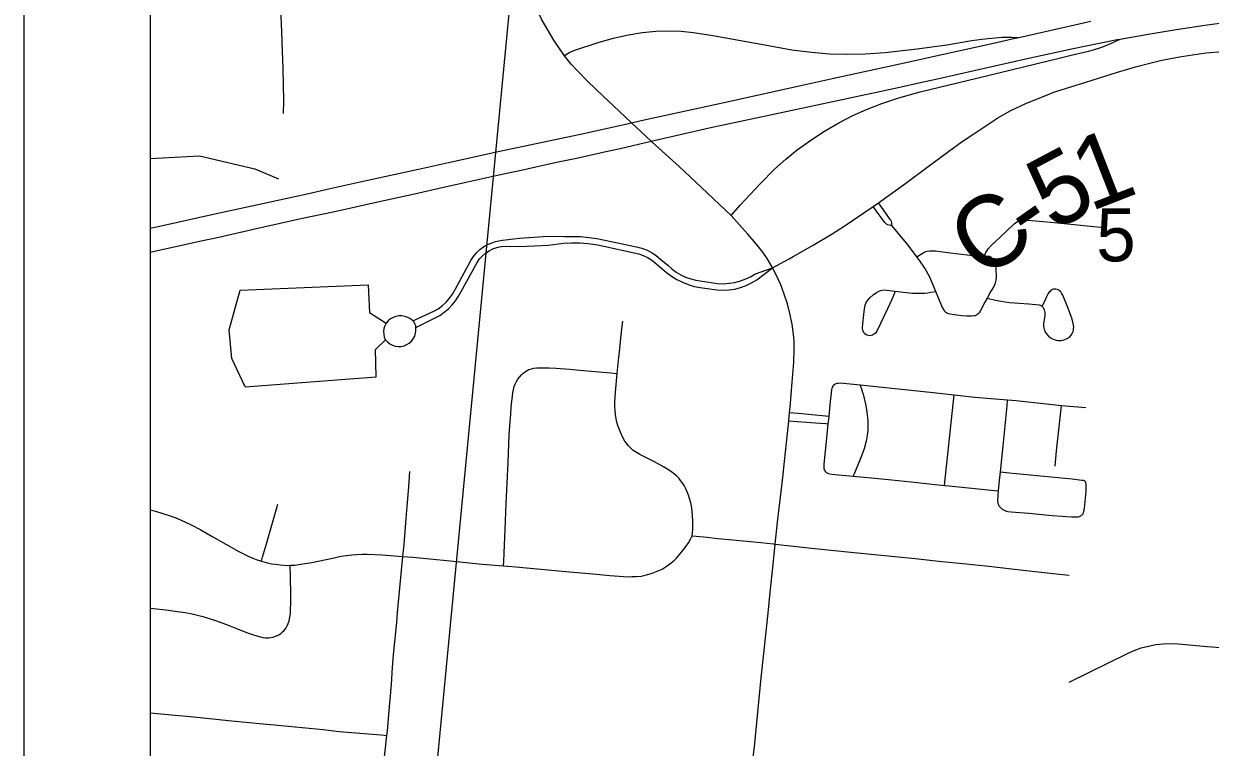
# Model space of a CAD drawing. Extents: x 0 to 34, y 0 to 22.
# Drawn here: x 22.416 to 23.354, y 13.976 to 14.548 of the extents above; entities that cross this region are included whole.
import ezdxf

# ---------------------------------------------------------------- set-up
doc = ezdxf.new("R2010")
doc.units = 0
for name, color, linetype in [('GM_X_City_Street', 7, 'Continuous'), ('GM_X_County_Road', 7, 'Continuous'), ('GM_X_County_Road_Text', 7, 'Continuous'), ('GM_X_Interchange_Ramps', 7, 'Continuous'), ('GM_X_Interstate_Route', 7, 'Continuous'), ('GM_X_Minor_River', 7, 'Continuous'), ('GM_X_Section', 7, 'Continuous'), ('GM_X_Section_Text', 7, 'Continuous'), ('SH_Border', 7, 'Continuous'), ('SH_Data', 7, 'Continuous')]:
    doc.layers.add(name, color=color, linetype=linetype)

msp = doc.modelspace()

# ---------------------------------------------------------------- linework, layer by layer
at = {"layer": 'GM_X_City_Street'}
for p, q in [((22.58739, 14.33718), (22.68845, 14.34132)), ((22.59139, 14.26067), (22.69501, 14.26859))]:
    msp.add_line(p, q, dxfattribs=at)
for points in [[(22.62172, 14.47673), (22.6219, 14.48664), (22.62129, 14.5124), (22.62056, 14.53306), (22.62023, 14.54176), (22.61961, 14.55852), (22.61954, 14.56349), (22.6202, 14.57179), (22.62145, 14.58727), (22.62216, 14.59842), (22.62247, 14.60549), (22.62223, 14.60887), (22.62184, 14.61264), (22.62153, 14.61578), (22.62078, 14.62011)], [(23.10245, 14.3882), (23.10128, 14.38825), (23.10023, 14.38836), (23.0993, 14.38868), (23.09833, 14.38921), (23.09764, 14.38974), (23.09695, 14.39055), (23.09473, 14.39346), (23.0917, 14.39775), (23.08779, 14.40327)], [(23.10245, 14.3882), (23.10241, 14.38934), (23.10233, 14.39027), (23.10206, 14.39135), (23.10156, 14.39237), (23.10116, 14.39297), (23.09587, 14.40054), (23.09197, 14.40612)], [(23.12209, 14.36354), (23.1152, 14.37267), (23.10245, 14.3882)], [(23.17561, 14.36415), (23.17623, 14.36564), (23.17671, 14.36682), (23.17719, 14.36762), (23.17773, 14.36848), (23.17864, 14.36977), (23.18089, 14.37229), (23.18833, 14.37937), (23.19922, 14.38957), (23.20133, 14.39112), (23.20208, 14.39157), (23.20328, 14.39209), (23.20445, 14.3925), (23.2057, 14.39266), (23.20702, 14.39266), (23.23064, 14.39062), (23.26993, 14.38661)], [(22.72394, 14.31296), (22.74046, 14.32042), (22.74394, 14.32251), (22.74719, 14.32494), (22.75019, 14.32769), (22.75288, 14.33073), (22.75527, 14.33401), (22.75731, 14.33753), (22.76978, 14.36054), (22.77173, 14.36371), (22.77407, 14.36661), (22.77676, 14.36919), (22.77974, 14.37141), (22.78299, 14.37323), (22.78644, 14.37462), (22.7891, 14.37556), (22.79184, 14.37624), (22.79463, 14.37668), (22.80808, 14.37829), (22.83063, 14.37989), (22.84374, 14.37943), (22.85014, 14.3796), (22.85653, 14.37941), (22.8629, 14.37885), (22.86924, 14.37795), (22.87551, 14.37668), (22.90069, 14.37147), (22.90493, 14.37032), (22.90901, 14.36872), (22.9129, 14.36669), (22.91656, 14.36426), (22.91993, 14.36145), (22.92531, 14.35676), (22.92851, 14.35396), (22.93196, 14.35146), (22.93562, 14.34929), (22.93947, 14.34747), (22.94346, 14.34601), (22.94758, 14.34491), (22.96469, 14.34236), (22.96926, 14.34224), (22.97382, 14.34254), (22.97834, 14.34328), (22.98276, 14.34444), (22.98706, 14.34601), (22.99119, 14.34798), (22.994, 14.34972), (23.00815, 14.35477)], [(22.72629, 14.30772), (22.74514, 14.31718), (22.74867, 14.31963), (22.75196, 14.3224), (22.75497, 14.32546), (22.75768, 14.32878), (22.76007, 14.33235), (22.76212, 14.33613), (22.77464, 14.35911), (22.77658, 14.36183), (22.77884, 14.36429), (22.78139, 14.36645), (22.78419, 14.36828), (22.78719, 14.36976), (22.79035, 14.37084), (22.79362, 14.37153), (22.79695, 14.37182), (22.80856, 14.37163), (22.83106, 14.37258), (22.84296, 14.37436), (22.84934, 14.37463), (22.85574, 14.37452), (22.86211, 14.37402), (22.86844, 14.37315), (22.87471, 14.37191), (22.89879, 14.36673), (22.90242, 14.36586), (22.90592, 14.36461), (22.90928, 14.363), (22.91244, 14.36104), (22.9154, 14.35877), (22.92071, 14.35426), (22.9244, 14.35102), (22.92834, 14.3481), (22.93253, 14.34554), (22.93692, 14.34335), (22.94148, 14.34155), (22.94618, 14.34014), (22.95099, 14.33915), (22.96423, 14.33733), (22.96895, 14.33709), (22.97366, 14.33732), (22.97833, 14.33802), (22.98291, 14.33918), (22.98736, 14.34079), (22.99161, 14.34283), (22.99565, 14.34529), (23.00815, 14.35477)], [(23.12209, 14.36354), (23.12721, 14.36674), (23.12823, 14.36726), (23.1292, 14.36769), (23.13041, 14.36803), (23.13214, 14.36828), (23.13452, 14.36827), (23.13693, 14.36811), (23.14669, 14.36679), (23.16401, 14.36469), (23.17561, 14.36415)], [(23.13717, 14.33615), (23.13516, 14.34102), (23.13233, 14.34732), (23.12841, 14.35447), (23.12459, 14.36022), (23.12209, 14.36354)], [(23.17561, 14.36415), (23.17654, 14.3641), (23.17883, 14.36399), (23.17947, 14.36389), (23.1802, 14.36365), (23.18101, 14.36316), (23.18153, 14.36272), (23.18218, 14.36211), (23.1827, 14.36134), (23.18308, 14.36074), (23.18348, 14.35983), (23.18384, 14.35896), (23.18421, 14.35765), (23.18457, 14.35471), (23.18477, 14.34735), (23.18455, 14.34501), (23.18437, 14.34391), (23.18402, 14.34272), (23.1829, 14.33999), (23.18075, 14.3363), (23.17769, 14.33071)], [(22.68845, 14.34132), (22.68971, 14.31959), (22.70267, 14.31106)], [(23.17769, 14.33071), (23.18446, 14.32926), (23.18862, 14.32836), (23.1953, 14.32748), (23.21072, 14.3263), (23.2189, 14.32556), (23.21961, 14.32537), (23.22033, 14.32502), (23.22101, 14.32453), (23.2215, 14.32405), (23.222, 14.32341), (23.22233, 14.32284), (23.22286, 14.32153), (23.22323, 14.31951), (23.22323, 14.31687), (23.22238, 14.31073), (23.22234, 14.3084), (23.22247, 14.30741), (23.22269, 14.30643), (23.22299, 14.30544), (23.22341, 14.30437), (23.22402, 14.30347), (23.22465, 14.30262), (23.22614, 14.30085), (23.22744, 14.29972), (23.22835, 14.29913), (23.2294, 14.29858), (23.23075, 14.29802), (23.23218, 14.29762), (23.23385, 14.29734), (23.23492, 14.29729), (23.23613, 14.2974), (23.23727, 14.29759), (23.2384, 14.29789), (23.24058, 14.29871), (23.24205, 14.29955), (23.24268, 14.30003), (23.24334, 14.30065), (23.24409, 14.30154), (23.24474, 14.30242), (23.24526, 14.30342), (23.24568, 14.30454), (23.24594, 14.30557), (23.24611, 14.30694), (23.24616, 14.30823), (23.24603, 14.30951), (23.24579, 14.31079), (23.24492, 14.31428), (23.24152, 14.3235), (23.23745, 14.33315), (23.23663, 14.33487), (23.23585, 14.3359), (23.23495, 14.33672), (23.23402, 14.33728), (23.23303, 14.33771), (23.232, 14.33792), (23.23114, 14.33796), (23.23019, 14.33783), (23.22929, 14.33753), (23.22852, 14.33706), (23.22781, 14.33648), (23.22724, 14.3359), (23.22659, 14.33521), (23.22603, 14.33449), (23.22539, 14.33341), (23.22461, 14.33195), (23.22384, 14.32998), (23.22273, 14.32762), (23.22118, 14.32467)], [(22.59139, 14.26067), (22.5809, 14.28319), (22.57861, 14.3057), (22.58739, 14.33718)], [(23.10515, 14.33599), (23.1023, 14.32983), (23.09894, 14.32251), (23.09638, 14.3168), (23.09063, 14.30475), (23.09, 14.30382), (23.08947, 14.30323), (23.0888, 14.30257), (23.08797, 14.30202), (23.08711, 14.30159), (23.08602, 14.30124), (23.08497, 14.30112), (23.08403, 14.3012), (23.08294, 14.30147), (23.08203, 14.30194), (23.08115, 14.30255), (23.08063, 14.30311), (23.08016, 14.30382), (23.07973, 14.30464), (23.07946, 14.30546), (23.0793, 14.30651), (23.07926, 14.30737), (23.07941, 14.31061), (23.0802, 14.31797), (23.08069, 14.32233), (23.08132, 14.3252), (23.08218, 14.32737), (23.0834, 14.32934), (23.08497, 14.33105), (23.08774, 14.33351), (23.09024, 14.33531), (23.09212, 14.33636), (23.09377, 14.33694), (23.09606, 14.33728), (23.09842, 14.33725), (23.11133, 14.33543), (23.11883, 14.33477), (23.12512, 14.33463), (23.12822, 14.33476), (23.13079, 14.33498), (23.13336, 14.33546), (23.13717, 14.33615)], [(23.17769, 14.33071), (23.176, 14.32761), (23.17223, 14.32041), (23.17147, 14.31916), (23.17074, 14.31839), (23.16989, 14.31778), (23.1692, 14.31734), (23.16831, 14.31698), (23.16755, 14.31679), (23.16526, 14.31659), (23.1614, 14.31657), (23.15785, 14.31682), (23.15366, 14.31728), (23.15015, 14.31787), (23.14708, 14.31856), (23.14623, 14.31888), (23.14554, 14.31924), (23.14486, 14.31969), (23.14425, 14.32033), (23.14367, 14.32121), (23.14204, 14.3244), (23.13717, 14.33615)], [(22.70267, 14.31106), (22.70165, 14.30901), (22.701, 14.30682), (22.70072, 14.30455), (22.70085, 14.30227), (22.70135, 14.30004), (22.70214, 14.29815)], [(22.70223, 14.29793), (22.70381, 14.2962), (22.70566, 14.29476), (22.70773, 14.29367), (22.70996, 14.29295), (22.71228, 14.29263), (22.71462, 14.29272), (22.71691, 14.29321), (22.71908, 14.2941), (22.72106, 14.29534), (22.7228, 14.29691), (22.72424, 14.29876), (22.72534, 14.30083), (22.72606, 14.30306), (22.72637, 14.30539), (22.72629, 14.30772), (22.72614, 14.30889), (22.72582, 14.31002), (22.72534, 14.31108), (22.72471, 14.31207), (22.72394, 14.31296)], [(22.72394, 14.31296), (22.72206, 14.31447), (22.71995, 14.31565), (22.71767, 14.31645), (22.71529, 14.31685), (22.71287, 14.31684), (22.71049, 14.31642), (22.70822, 14.3156), (22.70612, 14.31442), (22.70425, 14.31288), (22.70267, 14.31106)], [(22.94453, 14.14308), (22.94493, 14.1454), (22.94525, 14.14827), (22.94525, 14.15146), (22.94517, 14.15481), (22.94494, 14.15938), (22.94469, 14.16231), (22.94431, 14.16518), (22.94351, 14.16907), (22.94251, 14.17242), (22.94163, 14.17524), (22.94071, 14.17772), (22.93961, 14.18025), (22.93827, 14.18275), (22.93721, 14.18448), (22.93548, 14.18687), (22.93435, 14.18825), (22.93253, 14.19006), (22.93084, 14.19156), (22.92868, 14.1932), (22.92596, 14.1952), (22.92196, 14.19767), (22.91486, 14.20152), (22.9032, 14.20716), (22.90054, 14.20879), (22.89807, 14.21055), (22.89553, 14.21275), (22.8941, 14.21438), (22.8926, 14.21627), (22.8915, 14.21776), (22.89014, 14.22011), (22.88871, 14.22296), (22.88766, 14.22537), (22.88689, 14.22751), (22.88592, 14.23012), (22.88513, 14.23291), (22.88458, 14.23554), (22.88402, 14.2389), (22.88377, 14.24174), (22.88357, 14.2454), (22.88361, 14.24867), (22.88407, 14.25649), (22.88533, 14.27125), (22.88648, 14.28186), (22.88717, 14.28831), (22.88807, 14.29655), (22.88915, 14.30651), (22.88981, 14.31262)], [(22.69501, 14.26859), (22.6945, 14.29023), (22.70223, 14.29793)], [(22.79553, 14.11928), (22.79568, 14.12267), (22.79601, 14.12954), (22.79687, 14.14798), (22.79773, 14.16853), (22.79846, 14.18467), (22.7993, 14.20091), (22.79978, 14.21557), (22.80012, 14.22298), (22.80045, 14.22963), (22.80077, 14.23361), (22.80121, 14.23891), (22.80168, 14.24456), (22.80209, 14.24945), (22.80255, 14.25332), (22.80295, 14.25625), (22.80344, 14.25866), (22.80405, 14.26097), (22.80475, 14.26281), (22.80585, 14.26506), (22.8069, 14.26684), (22.80805, 14.26828), (22.80968, 14.27014), (22.81073, 14.27119), (22.81219, 14.27239), (22.81413, 14.2736), (22.8156, 14.27433), (22.81759, 14.27502), (22.81947, 14.27538), (22.82184, 14.27564), (22.82574, 14.27575), (22.83163, 14.27567), (22.83714, 14.27541), (22.84765, 14.27471), (22.85568, 14.27398), (22.88046, 14.2717), (22.88533, 14.27125)], [(23.05635, 14.26196), (23.05725, 14.26276), (23.0584, 14.26337), (23.05913, 14.26356), (23.05996, 14.26372), (23.06159, 14.26378), (23.0641, 14.26364), (23.07738, 14.26226)], [(23.05284, 14.23749), (23.054, 14.24925), (23.05505, 14.25847), (23.05523, 14.25953), (23.05552, 14.26052), (23.05594, 14.26138), (23.05635, 14.26196)], [(23.07182, 14.19023), (23.0728, 14.19239), (23.07416, 14.19536), (23.07805, 14.2045), (23.08081, 14.2121), (23.08269, 14.2192), (23.0832, 14.22232), (23.08359, 14.2267), (23.08371, 14.23033), (23.08359, 14.23425), (23.08313, 14.23849), (23.08258, 14.24288), (23.08178, 14.24707), (23.07991, 14.25491), (23.07955, 14.2561), (23.07871, 14.25885), (23.07791, 14.26089), (23.07738, 14.26226)], [(23.07738, 14.26226), (23.13269, 14.25648), (23.15155, 14.25446)], [(23.14408, 14.18289), (23.14435, 14.18544), (23.15155, 14.25446)], [(23.15155, 14.25446), (23.1679, 14.25271), (23.19394, 14.25043)], [(23.18818, 14.19349), (23.19027, 14.21416), (23.19133, 14.22462), (23.19348, 14.24584), (23.19394, 14.25043)], [(23.19394, 14.25043), (23.2007, 14.24984), (23.23658, 14.24607)], [(23.23149, 14.19808), (23.23267, 14.2103), (23.23444, 14.22685), (23.23596, 14.24099), (23.23658, 14.24607)], [(23.23658, 14.24607), (23.23963, 14.24575), (23.25571, 14.24429)], [(23.0216, 14.24057), (23.0285, 14.23989), (23.0501, 14.23776), (23.05284, 14.23749)], [(23.05219, 14.23158), (23.05277, 14.23685), (23.05284, 14.23749)], [(23.02092, 14.23378), (23.0276, 14.23329), (23.04591, 14.23195), (23.0502, 14.23169), (23.05219, 14.23158)], [(23.04946, 14.19449), (23.04921, 14.19514), (23.04903, 14.1959), (23.04887, 14.19726), (23.04888, 14.19852), (23.04892, 14.19964), (23.05092, 14.22017), (23.05219, 14.23158)], [(22.69894, 13.94555), (22.70098, 13.96349), (22.70337, 13.98538), (22.70373, 13.98874), (22.70488, 14.0018), (22.70698, 14.02565), (22.7079, 14.03924), (22.70897, 14.05161), (22.7111, 14.07447), (22.71188, 14.08248), (22.716, 14.12676), (22.71692, 14.13621), (22.71756, 14.14297), (22.71865, 14.15668), (22.7194, 14.16611), (22.72064, 14.1818), (22.72159, 14.1938)], [(23.04946, 14.19449), (23.05011, 14.19352), (23.05065, 14.19309), (23.05126, 14.19268), (23.05226, 14.19233), (23.05345, 14.19212), (23.05728, 14.1916), (23.07182, 14.19023)], [(23.07182, 14.19023), (23.08333, 14.18914), (23.10247, 14.18733), (23.12242, 14.1852), (23.13419, 14.18395), (23.14408, 14.18289)], [(23.18669, 14.17865), (23.18726, 14.1844), (23.18818, 14.19349)], [(23.18818, 14.19349), (23.19521, 14.1928), (23.24488, 14.18794), (23.25258, 14.18712), (23.25359, 14.18696), (23.25436, 14.18666), (23.25507, 14.18614), (23.25561, 14.18554)], [(23.14408, 14.18289), (23.14502, 14.18279), (23.18357, 14.17896), (23.18669, 14.17865)], [(23.18877, 14.16477), (23.18797, 14.16557), (23.18727, 14.16655), (23.1869, 14.16733), (23.18658, 14.16826), (23.18636, 14.16958), (23.18626, 14.17071), (23.18669, 14.17865)], [(23.18877, 14.16477), (23.18964, 14.16405), (23.19059, 14.16353), (23.19219, 14.16282), (23.19312, 14.16255), (23.19401, 14.16235), (23.19663, 14.16206), (23.21061, 14.16101), (23.22909, 14.1592), (23.24448, 14.15792), (23.24725, 14.15792), (23.24878, 14.158), (23.24969, 14.15811), (23.25061, 14.15829), (23.25172, 14.15882), (23.25236, 14.15925), (23.25286, 14.15966), (23.25332, 14.16019), (23.25389, 14.16131), (23.25417, 14.16224), (23.25436, 14.16344), (23.25456, 14.16492), (23.25596, 14.17798), (23.25611, 14.18109), (23.25611, 14.18359), (23.25584, 14.18492), (23.25561, 14.18554)], [(22.51637, 14.16352), (22.52043, 14.16258), (22.53222, 14.1589), (22.53648, 14.15728), (22.54022, 14.15571), (22.54411, 14.15387), (22.54858, 14.15174), (22.55622, 14.14767), (22.56592, 14.14216), (22.58649, 14.13054), (22.59375, 14.12686), (22.59732, 14.1253), (22.60014, 14.12423), (22.60419, 14.12299), (22.60615, 14.12238), (22.60902, 14.12167), (22.61229, 14.12094), (22.61527, 14.12051), (22.61913, 14.12007), (22.62458, 14.11971), (22.62696, 14.11975), (22.63068, 14.11993), (22.63359, 14.12024), (22.64407, 14.12194), (22.66173, 14.12571), (22.66688, 14.12683), (22.67143, 14.12754), (22.67575, 14.12807), (22.67939, 14.1284), (22.68389, 14.12865), (22.688, 14.12866), (22.69972, 14.12806), (22.716, 14.12676), (22.72385, 14.12614), (22.7373, 14.12489), (22.7533, 14.1232), (22.77866, 14.12059), (22.79553, 14.11928), (22.80529, 14.11851), (22.84176, 14.11511), (22.86899, 14.1126), (22.87949, 14.11161), (22.88691, 14.11112), (22.8938, 14.11069), (22.89693, 14.11077), (22.90073, 14.11094), (22.90427, 14.11128), (22.90759, 14.11198), (22.91031, 14.11266), (22.9131, 14.11344), (22.91569, 14.11447), (22.9184, 14.11555), (22.92085, 14.1168), (22.92341, 14.11826), (22.92593, 14.12), (22.92805, 14.12159), (22.93066, 14.12385), (22.93223, 14.12546), (22.93625, 14.13003), (22.93998, 14.13488), (22.94182, 14.13757), (22.94333, 14.14037), (22.94453, 14.14308), (22.94788, 14.14268), (22.95659, 14.14184), (22.96473, 14.14104), (22.97389, 14.14015), (22.98491, 14.1392), (22.99898, 14.13778), (23.00881, 14.13667), (23.01033, 14.13649)], [(22.60419, 14.12299), (22.60511, 14.12617), (22.60813, 14.13669), (22.61186, 14.14966), (22.61724, 14.16811)], [(23.01033, 14.13649), (23.0246, 14.1349), (23.03904, 14.13336), (23.07276, 14.12977), (23.12094, 14.125), (23.14192, 14.12285), (23.15846, 14.12121), (23.17896, 14.11917), (23.20615, 14.116), (23.23236, 14.11307), (23.24268, 14.11202)], [(22.51637, 14.08577), (22.51894, 14.08553), (22.52879, 14.08456), (22.53801, 14.08334), (22.54392, 14.08247), (22.54961, 14.08132), (22.55371, 14.08045), (22.55782, 14.07937), (22.56222, 14.07807), (22.56712, 14.07649), (22.57167, 14.07482), (22.57799, 14.07234), (22.58439, 14.06975), (22.5931, 14.06635), (22.59707, 14.06501), (22.60125, 14.06368), (22.6034, 14.0631), (22.60526, 14.0627), (22.60737, 14.06246), (22.60977, 14.06236), (22.61174, 14.06266), (22.61343, 14.06308), (22.61523, 14.06368), (22.61693, 14.06435), (22.61839, 14.06517), (22.61958, 14.06592), (22.62098, 14.06704), (22.62193, 14.06794), (22.62302, 14.06922), (22.62379, 14.07042), (22.62484, 14.07231), (22.62543, 14.07375), (22.62609, 14.07567), (22.62651, 14.07733), (22.62698, 14.0802), (22.62717, 14.08225), (22.62733, 14.09281), (22.62737, 14.09652), (22.62712, 14.1108), (22.62696, 14.11975)], [(23.2425, 14.02729), (23.28866, 14.05007), (23.29403, 14.05246), (23.29956, 14.05443), (23.30523, 14.05596), (23.311, 14.05706), (23.31684, 14.0577), (23.32271, 14.05788), (23.32858, 14.05761), (23.35165, 14.05565), (23.36951, 14.05414)], [(22.51637, 14.00318), (22.53617, 14.00133), (22.54802, 14.00018), (22.55588, 13.99941), (22.57808, 13.9972), (22.6083, 13.99421), (22.61451, 13.99362), (22.6253, 13.99255), (22.65308, 13.98988), (22.66562, 13.98854), (22.6819, 13.98712), (22.69894, 13.98574), (22.70337, 13.98538)]]:
    msp.add_lwpolyline(points, dxfattribs=at)
at = {"layer": 'GM_X_County_Road'}
msp.add_lwpolyline([(22.51637, 14.96793), (22.51637, 13.96654), (22.74129, 13.94338), (22.83652, 14.9377)], close=True, dxfattribs=at)
for points in [[(22.84363, 14.52233), (22.83538, 14.53467), (22.82566, 14.55121), (22.82192, 14.55926), (22.81856, 14.56749), (22.81538, 14.57649), (22.81285, 14.58505), (22.81067, 14.59436), (22.80932, 14.60194), (22.80828, 14.61085), (22.8079, 14.61722), (22.80776, 14.62728), (22.80712, 14.65654)], [(23.22829, 14.49268), (23.23213, 14.49404), (23.25576, 14.50153), (23.28064, 14.50928), (23.29489, 14.51352), (23.30744, 14.51686), (23.31588, 14.51879), (23.32987, 14.52141), (23.34346, 14.52363), (23.35117, 14.52458), (23.36337, 14.52568), (23.39044, 14.52668), (23.40355, 14.52647)], [(22.88246, 14.48269), (22.87393, 14.49065), (22.86227, 14.5019), (22.85402, 14.51042), (22.849, 14.51569), (22.84363, 14.52233)], [(23.11347, 14.42162), (23.13103, 14.43494), (23.14733, 14.44657), (23.15802, 14.45466), (23.1664, 14.46025), (23.18628, 14.47341), (23.19658, 14.47915), (23.20833, 14.48475), (23.22733, 14.49235), (23.22829, 14.49268)], [(22.97546, 14.39611), (22.95202, 14.41834), (22.93422, 14.43483), (22.91305, 14.45411), (22.91235, 14.45477), (22.89666, 14.46942), (22.88246, 14.48269)], [(23.08779, 14.40327), (23.09197, 14.40612), (23.11347, 14.42162)], [(23.00815, 14.35477), (23.02122, 14.36197), (23.0245, 14.36377), (23.04024, 14.3727), (23.05531, 14.38163), (23.06484, 14.38765), (23.08779, 14.40327)], [(23.00815, 14.35477), (23.00766, 14.35573), (23.00393, 14.36205), (23.00049, 14.36707), (22.99517, 14.37381), (22.98871, 14.38126), (22.97546, 14.39611)], [(23.02092, 14.23378), (23.0216, 14.24057), (23.02198, 14.24433), (23.02363, 14.26438), (23.02507, 14.2803), (23.02535, 14.29015), (23.02517, 14.29687), (23.02471, 14.30234), (23.02357, 14.31021), (23.02187, 14.31864), (23.01987, 14.32635), (23.01744, 14.33394), (23.01458, 14.34138), (23.01132, 14.34865), (23.00815, 14.35477)], [(23.0176, 14.20184), (23.01918, 14.21654), (23.02092, 14.23378)], [(23.01033, 14.13649), (23.01211, 14.15374), (23.01623, 14.18909), (23.0176, 14.20184)], [(22.96468, 13.87048), (22.96517, 13.87137), (22.9697, 13.88019), (22.97541, 13.89256), (22.9792, 13.9017), (22.98234, 13.91042), (22.98444, 13.91752), (22.98657, 13.92654), (22.98838, 13.93627), (22.99077, 13.95221), (22.99175, 13.95959), (22.99389, 13.97622), (22.99913, 14.03094), (23.00126, 14.05017), (23.00307, 14.06743), (23.00472, 14.0819), (23.00636, 14.09834), (23.00866, 14.12037), (23.01033, 14.13649)]]:
    msp.add_lwpolyline(points, dxfattribs=at)
at = {"layer": 'GM_X_Interchange_Ramps'}
for points in [[(22.9036, 14.54015), (22.8944, 14.53864), (22.88226, 14.53593), (22.87091, 14.53271), (22.85076, 14.5262), (22.84785, 14.52489), (22.84363, 14.52233)], [(23.20167, 14.53662), (23.19702, 14.53681), (23.18966, 14.53666), (23.18126, 14.53597), (23.17361, 14.53523), (23.16553, 14.53406), (23.14593, 14.53068), (23.12253, 14.52746), (23.0972, 14.5247), (23.0817, 14.52356), (23.06741, 14.52322), (23.05312, 14.52365), (23.03887, 14.52481), (23.02347, 14.52683), (23.00205, 14.53059), (22.96108, 14.53813), (22.94572, 14.54045), (22.93583, 14.54142), (22.92651, 14.54176), (22.91595, 14.54146), (22.90544, 14.54045), (22.9036, 14.54015)], [(22.97546, 14.39611), (22.98263, 14.40441), (22.9983, 14.42125), (23.00976, 14.43264), (23.01854, 14.44053), (23.02773, 14.44795), (23.03828, 14.45564), (23.04921, 14.46279), (23.06047, 14.46939), (23.07151, 14.47511), (23.08227, 14.47997), (23.09444, 14.48469), (23.10801, 14.48916), (23.12478, 14.49384), (23.16947, 14.50471), (23.23473, 14.5205), (23.24408, 14.52277), (23.25788, 14.52594), (23.26185, 14.52704), (23.26763, 14.52896), (23.27367, 14.53123), (23.28287, 14.53553)]]:
    msp.add_lwpolyline(points, dxfattribs=at)
at = {"layer": 'GM_X_Interstate_Route'}
for points in [[(22.51637, 14.38611), (22.52255, 14.38751), (22.56745, 14.3974), (22.60022, 14.40463), (22.6306, 14.41111), (22.64028, 14.41334), (22.65849, 14.41733), (22.68213, 14.42265), (22.70278, 14.42715), (22.72827, 14.43271), (22.75436, 14.43847), (22.79135, 14.44668), (22.86002, 14.46116), (22.89666, 14.46942), (22.90424, 14.47113), (22.96857, 14.48514), (23.03287, 14.49933), (23.0565, 14.50466), (23.10871, 14.51599), (23.14332, 14.52349), (23.18271, 14.53242), (23.2009, 14.53645), (23.20167, 14.53662), (23.21665, 14.54004), (23.25973, 14.54955)], [(22.51637, 14.36724), (22.52205, 14.36848), (22.55664, 14.376), (22.57058, 14.3791), (22.60147, 14.38616), (22.61907, 14.39007), (22.63546, 14.39364), (22.66097, 14.39915), (22.67856, 14.40306), (22.69495, 14.40654), (22.72526, 14.41331), (22.74466, 14.41766), (22.76467, 14.42211), (22.7956, 14.429), (22.80712, 14.43153), (22.83747, 14.43816), (22.85446, 14.44182), (22.87631, 14.44658), (22.88782, 14.44912), (22.91235, 14.45477), (22.95803, 14.4653), (23.01997, 14.47868), (23.0941, 14.49438), (23.10986, 14.49783), (23.1238, 14.50095), (23.13955, 14.50447), (23.20925, 14.52021), (23.2457, 14.52814), (23.28047, 14.53509), (23.28287, 14.53553), (23.30496, 14.53953), (23.32707, 14.54311), (23.3517, 14.54668), (23.36773, 14.54877)]]:
    msp.add_lwpolyline(points, dxfattribs=at)
at = {"layer": 'GM_X_Minor_River'}
msp.add_lwpolyline([(22.51637, 14.44129), (22.55517, 14.44335), (22.59897, 14.43297), (22.61778, 14.425)], dxfattribs=at)
at = {"layer": 'GM_X_Section'}
msp.add_lwpolyline([(23.81234, 14.84657), (23.73099, 13.84446), (22.74129, 13.94338), (22.83652, 14.9377)], close=True, dxfattribs=at)
at = {"layer": 'SH_Border'}
msp.add_lwpolyline([(22.51637, 14.97433), (22.51637, 13.46181), (28.78431, 13.46181)], dxfattribs=at)
at = {"layer": 'SH_Data'}
for p, q in [((22.41637, 20.36181), (22.41637, 13.36181)), ((22.51637, 20.26181), (22.51637, 13.46181))]:
    msp.add_line(p, q, dxfattribs=at)
msp.add_lwpolyline([(22.51637, 19.03183), (22.51637, 13.46181), (29.31637, 13.46181)], dxfattribs=at)

# ---------------------------------------------------------------- texts
at = {"layer": 'GM_X_County_Road_Text'}
for s, rotation, p in [('1', 21.26411, (23.25908, 14.39897)), ('5', 27.83464, (23.22969, 14.38334)), ('C', 35.12775, (23.17405, 14.3441)), ('-', 35.01728, (23.21219, 14.37094))]:
    msp.add_text(s, height=0.05682, rotation=rotation, dxfattribs=at).set_placement(p)
at = {"layer": 'GM_X_Section_Text'}
msp.add_text('5', height=0.04186, rotation=0.00001, dxfattribs=at).set_placement((23.264, 14.35989))

doc.saveas('drawing.dxf')
